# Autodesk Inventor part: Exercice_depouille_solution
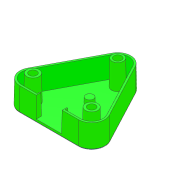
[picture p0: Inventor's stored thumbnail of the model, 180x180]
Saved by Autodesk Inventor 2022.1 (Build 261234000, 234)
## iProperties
Created: 2018-06
Part Number: Exercice_depouille_solution
Material: Générique
Document SubType Name: Modeling
Designer: Fabian Perrée
Density: 1 g/cm^3
Appearance: Par défaut
Mass: 7.16972 g
Surface Area: 90.7491 cm^2
Volume: 7.16972 cm^3
Author: Fabian Perrée
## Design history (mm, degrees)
sketch "Esquisse1"
  geometry: L1 (0, 0)-(0, -59.098); L2 (0, 0)-(7.75, 0); L3 (25.07, -11.743)-(7.07, -45.743); L4 (-7.07, -45.743)-(-25.07, -11.743); L5 (-18, 0)-(-7.75, 0); L6 (14.25, -19.25)-(11, -19.25); L7 (9, -21.25)-(14.25, -21.25); L8 (14.25, -21.25)-(14.25, -19.25); L9 (11, -19.25)-(11, -16); L10 (11, -16)-(9, -16); L11 (9, -16)-(9, -21.25); L12 (-23.524, -10.924)-(-5.524, -44.924); L13 (5.524, -44.924)-(23.524, -10.924); L14 (7.75, 0)-(7.75, -3); L15 (7.75, -3)-(8.75, -3); L16 (8.75, -3)-(8.75, -1.75); L17 (-7.75, -3)-(-8.75, -3); L18 (-8.75, -3)-(-8.75, -1.75); L19 (-7.75, 0)-(-7.75, -3); L20 (18, -1.75)-(8.75, -1.75); L21 (-8.75, -1.75)-(-18, -1.75); L22 (7.75, 0)-(18, 0); L23 (-7.75, 0)-(0, 0); C1 r 2.375 at (18, -8); C2 r 2.375 at (-18, -8); C3 r 2.375 at (0, -42); C4 r 3.75 at (18, -8); C5 r 3.75 at (0, -42); C6 r 3.75 at (-18, -8); C7 r 2.375 at (0, -24.75); A1 r 8 centre (18, -8) between (25.07, -11.743) and (18, 0); A2 r 8 centre (0, -42) between (-7.07, -45.743) and (7.07, -45.743); A3 r 8 centre (-18, -8) between (-18, 0) and (-25.07, -11.743); A4 r 6.25 centre (-18, -8) between (-18, -1.75) and (-23.524, -10.924); A5 r 6.25 centre (0, -42) between (-5.524, -44.924) and (5.524, -44.924); A6 r 6.25 centre (18, -8) between (23.524, -10.924) and (18, -1.75); 1 further point
  constraints: 46 end point, 13 centre point, 12 point on circle, 10 tangent, 8 perpendicular, 7 point on line, 6 equal radius, 4 horizontal, 4 symmetric about line, 3 coincident, 3 vertical, 2 concentric, 1 parallel, 6 other
  dimensions: "d0" = 34 vertical distance of C3.centre C1.centre; "d1" = 2 distance of L7.end L6.start; "d2" = 3.25 distance of L6.end L9.end; "d3" = 9 distance between parallel lines of L1 L11; "d4" = 13.25 distance from line of C1.centre L7; "d5" = 8 radius of A1; "d6" = 7.5 diameter of C4; "d7" = 36 distance of C2.centre C1.centre; "d8" = 4.75 diameter of C1; "d9" = 4.75 diameter of C7; "d10" = 16.75 vertical distance of C1.centre C7.centre; "d11" = 1.75 radial gap between concentric circles of A1 A6; "d12" = 1 distance of L14.end L15.end; "d13" = 15.5 diameter of L14 L1; "d14" = 3 distance of L2.end L14.end; "d41" = 5.25 distance of L10.end L7.start
extrude "Extrusion1" new body sketch "Esquisse1" distance "d15" = 1.75; taper "d16" = 0 deg
extrude "Extrusion2" join sketch "Esquisse1" distance "d17" = 12.5; taper "d18" = 0 deg
extrude "Extrusion3" join sketch "Esquisse1" distance "d19" = 15.25; taper "d20" = 0 deg
extrude "Extrusion4" join sketch "Esquisse1" distance "d21" = 3.25; taper "d22" = 0 deg
node "Plan de construction1"
fillet "Congé1" dims "d40" = 0.5
feature "Dépouille de face1" dims angle "d50" = 1 deg
feature "Dépouille de face2" dims angle "d51" = 3 deg
node "Solide1"
other parameters: "d23" = 3.25
